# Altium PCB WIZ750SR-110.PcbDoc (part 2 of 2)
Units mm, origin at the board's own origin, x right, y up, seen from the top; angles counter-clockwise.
Board outline 63 x 45 mm, 4 copper layers (Top Layer, Internal Plane 1, Internal Plane 2, Bottom Layer); 95 components, 91 nets, 361 pads, 264 vias.
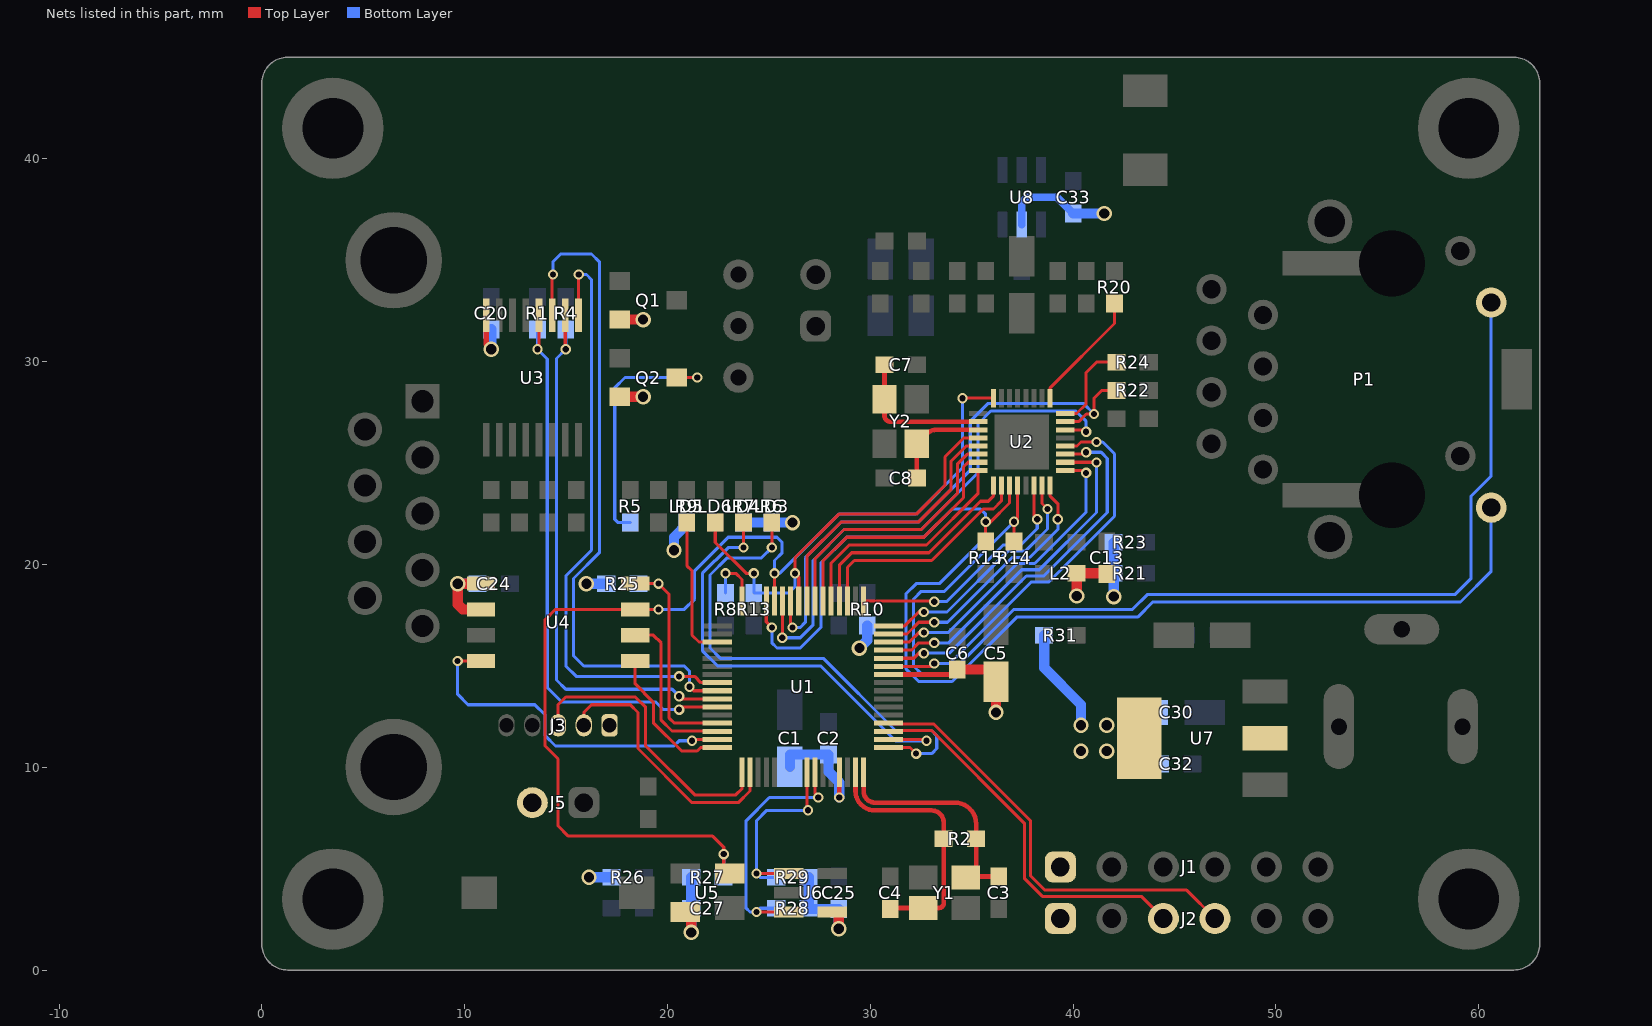
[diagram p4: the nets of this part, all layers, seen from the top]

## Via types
v1: diameter 0.762, hole 0.508, Top Layer to Bottom Layer, tented both sides, 186 vias
v2: diameter 0.508, hole 0.305, Top Layer to Bottom Layer, tented both sides, 78 vias

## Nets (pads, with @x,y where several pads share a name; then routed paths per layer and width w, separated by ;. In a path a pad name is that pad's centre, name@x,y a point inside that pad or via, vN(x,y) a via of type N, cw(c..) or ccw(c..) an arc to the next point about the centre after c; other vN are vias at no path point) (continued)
NetQ2_3: Q2.3 R5.1 | length 12.6
  Top Layer w0.152: Q2.3@20.45,29.21 v2(21.463,29.21)
  Bottom Layer w0.152: R5.1@18.161,22.06 17.564,22.06 17.399,22.225 17.399,28.702 17.907,29.21 v2(21.463,29.21)
NetR8_2: R8.2 U1.32 | length 3
  Top Layer w0.152: v2(22.86,19.558) 23.368,19.558 23.67,19.256 U1.32@23.67,18.195
  Bottom Layer w0.152: R8.2@22.86,18.58 v2(22.86,19.558)
NetR20_2: R20.2 U2.25 | length 6
  Top Layer w0.152: U2.25@38.865,28.185 38.865,28.705 42.037,31.877 R20.2@42.037,32.855
NetR24_2: R24.2 U2.24 | length 4.5
  Top Layer w0.152: U2.24@39.615,27.435 40.168,27.435 40.64,27.907 40.64,29.464 41.148,29.972 R24.2@42.126,29.972
PB_04: U1.24 U2.5 | length 13.7
  Top Layer w0.152: U1.24@26.87,18.195 26.87,20.393 28.575,22.098 32.385,22.098 33.985,23.698 33.985,25.095 34.725,25.835 U2.5@35.315,25.835
PB_05: LD6.2 R13.2 U1.25 U2.4 | length 21.8
  Top Layer w0.152: LD6.2@22.352,22.06 22.352,21.082 23.876,19.558 v2(24.257,19.558) ; U1.25@26.47,18.195 26.47,19.377 v2(26.289,19.558) 26.289,20.32 28.448,22.479 32.258,22.479 33.68,23.901 33.68,25.298 34.617,26.235 U2.4@35.315,26.235
  Bottom Layer w0.152: v2(24.257,19.558) R13.2@24.257,18.58 25.971,18.58 26.289,18.898 v2(26.289,19.558)
PB_06: U1.16 U2.15 | length 12.1
  Top Layer w0.152: U1.16@30.895,16.97 31.702,16.97 32.385,17.653 v2(32.639,17.653) ; U2.15@38.465,23.885 38.465,23.003 v2(38.735,22.733)
  Bottom Layer w0.152: v2(32.639,17.653) 33.782,17.653 36.779,20.65 37.643,20.65 38.735,21.742 v2(38.735,22.733)
PB_07: U1.17 U2.14 | length 12.2
  Top Layer w0.152: U1.17@29.67,18.195 33.113,18.195 v2(33.147,18.161) ; U2.14@38.065,23.885 38.065,22.387 v2(38.227,22.225)
  Bottom Layer w0.152: v2(33.147,18.161) 33.757,18.161 36.551,20.955 37.414,20.955 38.227,21.768 v2(38.227,22.225)
PB_09: U1.19 U2.10 | length 11.4
  Top Layer w0.152: U1.19@28.87,18.195 28.87,19.853 29.21,20.193 33.02,20.193 35.56,22.733 36.068,22.733 36.465,23.13 U2.10@36.465,23.885
PB_10: U1.20 U2.9 | length 11.3
  Top Layer w0.152: U1.20@28.47,18.195 28.47,19.961 29.083,20.574 32.893,20.574 35.433,23.114 35.814,23.114 36.065,23.365 U2.9@36.065,23.885
PB_11: U1.21 U2.8 | length 11.7
  Top Layer w0.152: U1.21@28.07,18.195 28.07,20.069 28.956,20.955 32.766,20.955 35.315,23.504 U2.8@35.315,24.635
PB_12: U1.22 U2.7 | length 12.5
  Top Layer w0.152: U1.22@27.67,18.195 27.67,20.177 28.829,21.336 32.639,21.336 34.595,23.292 34.595,24.81 34.82,25.035 U2.7@35.315,25.035
PB_13: U1.23 U2.6 | length 13.1
  Top Layer w0.152: U1.23@27.27,18.195 27.27,20.285 28.702,21.717 32.512,21.717 34.29,23.495 34.29,24.943 34.782,25.435 U2.6@35.315,25.435
PB_14: R22.1 U1.26 U2.23 | length 27.9
  Top Layer w0.152: U1.26@26.07,18.195 26.07,16.983 v2(26.162,16.891) ; U2.23@39.615,27.035 40.271,27.035 40.648,27.412 v2(41.027,27.412) 41.027,28.194 41.408,28.575 R22.1@42.126,28.575
  Bottom Layer w0.152: v2(26.162,16.891) 26.543,16.891 26.797,17.145 26.797,20.32 28.575,22.098 32.385,22.098 34.925,24.638 34.925,27.051 35.814,27.94 40.499,27.94 v2(41.027,27.412)
PB_15: U1.27 U2.22 | length 26.5
  Top Layer w0.152: v2(25.654,16.383) 25.67,16.399 U1.27@25.67,18.195 ; U2.22@39.615,26.635 40.548,26.635 v2(40.64,26.543)
  Bottom Layer w0.152: v2(25.654,16.383) 26.543,16.383 27.178,17.018 27.178,20.193 28.702,21.717 32.512,21.717 35.306,24.511 35.306,26.924 35.941,27.559 40.132,27.559 40.64,27.051 v2(40.64,26.543)
PD_00: U1.11 U2.20 | length 20
  Top Layer w0.152: U1.11@30.895,14.97 33.004,14.97 v2(33.147,15.113) ; U2.20@39.615,25.835 40.186,25.835 40.386,26.035 v2(41.148,26.035)
  Bottom Layer w0.152: v2(33.147,15.113) 33.909,15.113 37.922,19.126 38.786,19.126 42.037,22.377 42.037,25.451 41.453,26.035 v2(41.148,26.035)
PD_01: U1.12 U2.19 | length 18.7
  Top Layer w0.152: U1.12@30.895,15.37 32.134,15.37 32.385,15.621 v2(32.639,15.621) ; U2.19@39.615,25.435 40.548,25.435 v2(40.64,25.527)
  Bottom Layer w0.152: v2(32.639,15.621) 33.884,15.621 37.694,19.431 38.557,19.431 41.681,22.555 41.681,25.222 41.377,25.527 v2(40.64,25.527)
PD_02: U1.13 U2.18 | length 17.1
  Top Layer w0.152: U1.13@30.895,15.77 32.026,15.77 32.385,16.129 v2(33.147,16.129) ; U2.18@39.615,25.035 41.132,25.035 v2(41.148,25.019)
  Bottom Layer w0.152: v2(33.147,16.129) 33.858,16.129 37.465,19.736 38.329,19.736 41.148,22.555 v2(41.148,25.019)
PD_03: U1.14 U2.17 | length 15.4
  Top Layer w0.152: U1.14@30.895,16.17 31.918,16.17 32.385,16.637 v2(32.639,16.637) ; U2.17@39.615,24.635 40.516,24.635 v2(40.64,24.511)
  Bottom Layer w0.152: v2(32.639,16.637) 33.833,16.637 37.236,20.041 38.1,20.041 40.64,22.581 v2(40.64,24.511)
PD_04: U1.15 U2.16 | length 12.8
  Top Layer w0.152: U1.15@30.895,16.57 31.81,16.57 32.385,17.145 v2(33.147,17.145) ; U2.16@38.865,23.885 38.865,23.365 39.243,22.987 v2(39.243,22.225)
  Bottom Layer w0.152: v2(33.147,17.145) 33.807,17.145 37.008,20.345 37.871,20.345 39.243,21.717 v2(39.243,22.225)
PHY_AD0: P1.L4 R15.2 U1.29 U2.11 | length 65.5
  Top Layer w0.152: U1.29@24.87,18.195 24.87,17.167 v2(25.146,16.891) ; R15.2@35.687,21.12 v2(35.687,22.098) 35.941,22.098 36.865,23.022 U2.11@36.865,23.885
  Bottom Layer w0.152: v2(25.146,16.891) 25.146,16.129 25.4,15.875 26.543,15.875 27.559,16.891 27.559,20.066 28.829,21.336 32.639,21.336 34.036,22.733 35.433,22.733 35.687,22.479 v2(35.687,22.098) 35.687,21.336 33.401,19.05 32.258,19.05 31.75,18.542 31.75,14.859 32.385,14.224 34.036,14.224 37.211,17.399 43.18,17.399 43.923,18.142 59.097,18.142 60.61,19.655 P1.L4@60.61,22.8
PHY_AD3: P1.L2 R14.2 U2.12 | length 56.3
  Top Layer w0.152: R14.2@37.084,21.12 v2(37.084,22.098) 37.265,22.279 U2.12@37.265,23.885
  Bottom Layer w0.152: v2(37.084,22.098) 33.655,18.669 32.512,18.669 32.131,18.288 32.131,14.986 32.512,14.605 33.909,14.605 37.084,17.78 42.926,17.78 43.669,18.523 58.843,18.523 59.605,19.285 59.605,23.349 60.61,24.354 P1.L2@60.61,32.91
RESETN: R27.1 U1.28 U2.32 U4.3 U5.2 | length 55.3
  Top Layer w0.152: v2(19.558,17.78) U4.3@18.405,17.78 14.478,17.78 13.97,17.272 13.97,11.049 14.605,10.414 14.605,7.112 15.113,6.604 22.225,6.604 22.771,6.058 v2(22.771,5.715) 22.771,5.06 U5.2@23.071,4.76 ; U1.28@25.27,18.195 25.27,19.555 v2(25.273,19.558) ; v2(34.544,28.194) 36.056,28.194 U2.32@36.065,28.185
  Bottom Layer w0.152: v2(19.558,17.78) 20.828,17.78 21.336,18.288 21.336,19.685 22.987,21.336 25.4,21.336 25.654,21.082 25.654,20.574 25.273,20.193 v2(25.273,19.558) 25.527,19.558 28.448,22.479 32.258,22.479 34.544,24.765 v2(34.544,28.194) ; R27.1@22.771,4.572 v2(22.771,5.715)
SCL1: R29.1 U1.57 U6.1 | length 9.9
  Top Layer w0.152: v2(24.384,4.76) U6.1@25.976,4.76 ; U1.57@26.87,9.745 26.87,7.928 v2(26.924,7.874)
  Bottom Layer w0.152: R29.1@25.362,4.572 24.572,4.572 v2(24.384,4.76) 24.384,7.366 24.892,7.874 v2(26.924,7.874)
SDA1: R28.1 U1.58 U6.3 | length 12.9
  Top Layer w0.152: v2(24.384,2.86) U6.3@25.976,2.86 ; U1.58@27.27,9.745 27.27,8.671 v2(27.432,8.509)
  Bottom Layer w0.152: R28.1@25.362,3.048 24.572,3.048 v2(24.384,2.86) 24.064,2.86 23.876,3.048 23.876,7.366 25.019,8.509 v2(27.432,8.509)
SPI_MISO1: U1.47 U4.8 | length 17.4
  Top Layer w0.152: v2(9.652,15.24) U4.8@10.805,15.24 ; v2(21.209,11.303) 21.276,11.37 U1.47@22.445,11.37
  Bottom Layer w0.152: v2(9.652,15.24) 9.652,13.589 10.16,13.081 13.462,13.081 13.97,12.573 13.97,11.557 14.478,11.049 20.32,11.049 20.574,11.303 v2(21.209,11.303)
SPI_MOSI1: U1.48 U4.1 | length 7.2
  Top Layer w0.152: U4.1@18.405,15.24 18.405,14.107 19.304,13.208 19.304,12.192 20.701,10.795 21.463,10.795 21.638,10.97 U1.48@22.445,10.97
SPI_SCLK1: U1.46 U4.2 | length 8.2
  Top Layer w0.152: U4.2@18.405,16.51 19.304,16.51 19.685,16.129 19.685,12.319 20.221,11.783 22.445,11.783 U1.46@22.445,11.77
SPI_SSEL1: R25.1 U1.45 U4.4 | length 11.4
  Top Layer w0.152: U4.4@18.405,19.05 v2(19.558,19.05) 20.066,18.542 20.066,12.446 20.342,12.17 U1.45@22.445,12.17
  Bottom Layer w0.152: R25.1@18.58,19.05 v2(19.558,19.05)
STATUS: LD5.2 U1.35 | length 7
  Top Layer w0.152: LD5.2@20.955,22.06 20.955,19.939 21.209,19.685 21.209,16.51 21.549,16.17 U1.35@22.445,16.17
STATUS_LED0: LD3.2 U1.1 | length 24.6
  Top Layer w0.152: v2(25.146,20.828) LD3.2@25.146,22.06 ; U1.1@30.895,10.97 31.956,10.97 v2(32.258,10.668)
  Bottom Layer w0.152: v2(25.146,20.828) 24.638,20.32 22.943,20.32 22.098,19.475 22.098,15.875 22.606,15.367 27.686,15.367 31.242,11.811 33.02,11.811 33.274,11.557 33.274,10.922 33.02,10.668 v2(32.258,10.668)
STATUS_LED1: LD4.2 U1.2 | length 22.4
  Top Layer w0.152: v2(23.749,20.828) LD4.2@23.749,22.06 ; U1.2@30.895,11.37 32.699,11.37 v2(32.766,11.303)
  Bottom Layer w0.152: v2(23.749,20.828) 22.987,20.828 21.717,19.558 21.717,15.748 22.479,14.986 27.559,14.986 31.242,11.303 v2(32.766,11.303)
SWCLK: J3.3 U1.49 | length 14.3
  Top Layer w0.152: J3.3@14.605,12.065 14.605,13.081 14.986,13.462 18.415,13.462 18.923,12.954 18.923,11.049 21.336,8.636 23.368,8.636 23.67,8.938 U1.49@23.67,9.745
SWDIO: J3.2 U1.50 | length 13.2
  Top Layer w0.152: J3.2@15.875,12.065 15.875,12.7 16.256,13.081 18.161,13.081 18.542,12.7 18.542,10.922 21.209,8.255 23.495,8.255 24.07,8.83 U1.50@24.07,9.745
U_CTS0: U1.40 U3.9 | length 30.1
  Top Layer w0.152: U3.9@15.61,32.284 15.61,34.279 v2(15.621,34.29) ; v2(20.574,14.478) 21.336,14.478 21.644,14.17 U1.40@22.445,14.17
  Bottom Layer w0.152: v2(15.621,34.29) 16.002,34.29 16.256,34.036 16.256,20.701 14.986,19.431 14.986,14.986 15.494,14.478 v2(20.574,14.478)
U_RTS0: U1.41 U3.11 | length 33.5
  Top Layer w0.152: U3.11@14.31,32.284 14.31,34.249 v2(14.351,34.29) ; v2(21.082,13.97) 21.282,13.77 U1.41@22.445,13.77
  Bottom Layer w0.152: v2(14.351,34.29) 14.351,34.925 14.732,35.306 16.256,35.306 16.637,34.925 16.637,20.574 15.367,19.304 15.367,15.494 15.875,14.986 20.828,14.986 21.082,14.732 v2(21.082,13.97)
U_RXD0: R1.2 U1.43 U3.12 | length 28.4
  Top Layer w0.152: v2(13.589,30.607) 13.66,30.678 U3.12@13.66,32.284 ; v2(20.574,12.84) 20.704,12.97 U1.43@22.445,12.97
  Bottom Layer w0.152: R1.2@13.589,31.585 v2(13.589,30.607) 14.072,30.124 14.072,13.933 14.796,13.208 19.431,13.208 19.799,12.84 v2(20.574,12.84)
U_RXD2: J2.4 U1.4 | length 21.7
  Top Layer w0.152: U1.4@30.895,12.17 30.943,12.122 33.14,12.122 37.897,7.365 37.897,4.648 38.608,3.937 45.593,3.937 J2.4@46.99,2.54
U_TXD0: R4.2 U1.42 U3.10 | length 27.5
  Top Layer w0.152: U3.10@14.96,32.284 14.96,30.633 v2(14.986,30.607) ; v2(20.574,13.5) 20.704,13.37 U1.42@22.445,13.37
  Bottom Layer w0.152: R4.2@14.986,31.585 v2(14.986,30.607) 14.529,30.15 14.529,14.3 14.986,13.843 20.231,13.843 v2(20.574,13.5)
U_TXD2: J2.3 U1.3 | length 19
  Top Layer w0.152: U1.3@30.895,11.77 30.943,11.818 33.013,11.818 37.592,7.239 37.592,4.522 38.482,3.632 43.358,3.632 J2.3@44.45,2.54
VCC_3.3V: C1.1 C2.2 C5.1 C6.2 C13.2 C20.2 C24.1 C25.2 C27.2 C30.1 C32.2 C33.1 J1.1 J2.1 J3.1 J5.2 L2.1 Q1.2 Q2.2 R6.2 R7.2 R9.2 R10.2 R21.1 R23.1 R25.2 R26.2 R27.2 R28.2 R29.2 R31.1 U1.10 U1.61 U3.16 U4.5 U4.6 U5.4 U6.4 U7.2 U7.4 U8.5 | length 55.5
  Top Layer w0.229: v2(28.47,8.509) U1.61@28.47,9.745 ; U1.10@30.895,14.57 34.039,14.57 C6.2@34.29,14.821
  Top Layer w0.254: U3.16@11.06,32.284 11.06,30.85 v1(11.303,30.607)
  Top Layer w0.508: U4.6@10.805,17.78 9.906,17.78 9.652,18.034 v1(9.652,19.05) U4.5@10.805,19.05 ; Q2.2@17.65,28.26 v1(18.796,28.26) ; Q1.2@17.65,32.07 v1(18.796,32.07) ; U5.4@20.871,2.86 21.171,2.56 v1(21.171,1.854) ; U6.4@28.126,2.86 28.448,2.86 v1(28.448,2.032) ; C6.2@34.29,14.821 36.195,14.821 C5.1@36.195,14.221 v1(36.195,12.7) ; v1(40.17,18.44) L2.1@40.17,19.558 41.618,19.558 C13.2@41.656,19.52
  Bottom Layer w0.381: U8.5@37.465,36.76 37.465,37.846 37.719,38.1 39.205,38.1 C33.1@40.005,37.3
  Bottom Layer w0.508: v1(9.652,19.05) C24.1@10.63,19.05 ; v1(11.303,30.607) C20.2@11.303,31.585 ; v1(16.002,19.05) R25.2@16.98,19.05 ; v1(16.129,4.572) R26.2@17.234,4.572 ; v1(20.32,20.701) 20.32,21.344 20.955,21.979 R9.2@20.955,22.06 ; v1(21.171,1.854) C27.2@21.171,3.048 R27.2@21.171,4.572 ; R7.2@23.749,22.06 R6.2@25.146,22.06 v1(26.162,22.06) ; C1.1@26.035,10.03 26.035,10.63 C2.2@27.94,10.63 27.94,9.779 28.47,9.249 v2(28.47,8.509) ; R29.2@26.962,4.572 R28.2@26.962,3.048 27,3.01 C25.2@28.448,3.01 v1(28.448,2.032) ; v1(29.464,15.875) 29.845,16.256 R10.2@29.845,16.98 ; R31.1@38.57,16.51 38.57,14.897 40.386,13.081 v1(40.386,12.065) ; C33.1@40.005,37.3 v1(41.529,37.3) ; v1(41.999,18.415) R21.1@41.999,19.558 R23.1@41.999,21.082
  other v1: 40.386,10.795 41.656,10.795 41.656,12.065
XIN: C4.2 R2.2 U1.63 Y1.3 | length 12.9
  Top Layer w0.229: U1.63@29.27,9.745 29.27,8.825 ccw(c30.226,8.825) 30.226,7.869 33.02,7.869 cw(c33.02,7.272) 33.617,7.272 R2.2@33.617,6.477 33.617,3.302 cw(c33.375,3.302) 33.375,3.06 Y1.3@32.605,3.06 31.038,3.06 ccw(c31.038,3.01) C4.2@30.988,3.01
XOUT: C3.2 R2.1 U1.64 Y1.1 | length 11.8
  Top Layer w0.229: U1.64@29.67,9.745 29.67,8.811 ccw(c30.226,8.811) 30.226,8.255 34.163,8.255 cw(c34.163,7.201) 35.217,7.201 R2.1@35.217,6.477 35.217,5.072 cw(c34.755,5.072) 34.755,4.61 C3.2@36.322,4.61
XTAL1: C7.2 U2.2 Y2.1 | length 7.3
  Top Layer w0.229: C7.2@30.696,29.845 Y2.1@30.696,28.151 30.696,27.327 ccw(c30.988,27.327) 30.988,27.035 U2.2@35.315,27.035
XTAL2: C8.2 U2.3 Y2.3 | length 5
  Top Layer w0.229: C8.2@32.296,24.257 Y2.3@32.296,25.951 32.795,26.45 cw(c33.242,26.002) 33.242,26.635 U2.3@35.315,26.635
pads on no net: P1. P1.R4 P1.R5 P1.R6 P2.1 P2.4 P2.6 P2.9 SW2.2 U1.30 U1.31 U1.33 U1.34 U1.38 U1.44 U1.51 U1.52 U1.53 U1.54 U1.55 U1.56 U1.59 U1.60 U2.1 U2.21

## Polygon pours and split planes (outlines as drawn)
CH_GND on Top Layer "Top Layer-NET" (solid, remove dead copper, pour order 18): 62.103,37.211 54.483,37.211 53.34,36.068 51.943,36.068 50.8,37.211 46.99,37.211 46.736,37.465 46.736,41.91 46.482,42.164 9.398,42.164 9.186,41.952 9.144,41.91 9.144,40.188 9.144,31.242 8.89,30.988 2.921,30.988 2.667,30.734 2.667,14.224 2.921,13.97 8.89,13.97 9.144,13.716 9.144,7.493 8.89,7.239 7.493,7.239 7.239,6.985 7.239,0.889 6.985,0.635 0.889,0.635 0.635,0.889 0.635,44.069 0.889,44.323 62.103,44.323 62.357,44.069 62.357,37.465 62.103,37.211
5V on Top Layer "Top Layer-NET" (solid, remove dead copper, pour order 0): 53.848,14.478 53.848,10.16 53.594,9.906 51.689,9.906 51.435,10.16 51.435,12.7 51.181,12.954 50.927,12.954 46.99,12.954 46.736,13.208 46.736,17.272 46.99,17.526 53.594,17.526 53.848,17.272
VCC_3.3V on Top Layer "Top Layer-NET" (solid, remove dead copper, pour order 4): 49.657,12.319 50.546,12.319 50.8,12.065 50.8,11.938 50.8,10.795 50.546,10.541 50.292,10.541 46.609,10.541 46.355,10.287 46.355,10.16 46.355,8.382 46.101,8.128 45.974,8.128 40.005,8.128 39.751,8.382 39.751,8.509 39.751,14.478 40.005,14.732 40.132,14.732 46.101,14.732 46.355,14.478 46.355,14.351 46.355,12.573 46.609,12.319
GND on Top Layer "Top Layer-GND" (solid, remove dead copper, pour order 16): 9.906,29.591 4.445,29.591 4.191,29.337 4.191,27.559 4.191,16.002 4.445,15.748 4.699,15.748 10.414,15.748 10.668,15.494 10.668,15.24 10.668,5.969 10.414,5.715 10.16,5.715 9.017,5.715 8.763,5.461 8.763,5.207 8.763,1.016 9.017,0.762 9.144,0.762 53.721,0.762 53.975,1.016 53.975,1.143 53.975,8.763 54.229,9.017 54.356,9.017 62.103,9.017 62.357,9.271 62.357,9.525 62.357,17.78 62.103,18.034 61.849,18.034 45.466,18.034 45.212,18.288 45.212,18.542 45.212,40.513 44.958,40.767 44.704,40.767 10.922,40.767 10.668,40.513 10.668,40.132 10.668,29.845 10.414,29.591
GND on Top Layer "Top Layer-GND" (solid, remove dead copper, pour order 22): 33.401,32.131 33.401,30.353 34.798,28.956 41.91,28.956 42.037,29.083 42.037,32.131
CH_GND on Bottom Layer "Top Layer-NET" (solid, remove dead copper, pour order 20): 62.357,42.037 62.357,37.465 62.103,37.211 54.864,37.211 54.61,36.957 54.61,20.32 54.356,20.066 50.927,20.066 50.673,20.32 50.673,36.957 50.419,37.211 46.99,37.211 46.736,37.465 46.736,41.91 46.482,42.164 9.398,42.164 9.144,41.91 9.144,31.242 8.89,30.988 2.921,30.988 2.667,30.734 2.667,14.224 2.921,13.97 8.89,13.97 9.144,13.716 9.144,7.493 8.906,7.255 7.509,7.255 7.239,6.985 7.239,0.889 6.985,0.635 0.889,0.635 0.635,0.889 0.635,44.069 0.889,44.323 62.103,44.323 62.357,44.069
5V on Bottom Layer "Top Layer-NET" (solid, remove dead copper, pour order 2): 51.435,16.764 51.435,14.859 51.181,14.605 49.911,14.605 46.99,14.605 46.736,14.859 46.736,17.272 46.99,17.526 51.181,17.526 51.435,17.272
VCC_3.3V on Bottom Layer "Top Layer-NET" (solid, remove dead copper, pour order 6): 44.704,12.319 44.704,9.652 44.45,9.398 44.323,9.398 40.005,9.398 39.751,9.652 39.751,9.779 39.751,13.462 40.005,13.716 40.259,13.716 44.45,13.716 44.704,13.462
GND on Bottom Layer "Top Layer-GND" (solid, remove dead copper, pour order 14): 9.906,29.591 4.445,29.591 4.191,29.337 4.191,27.559 4.191,16.002 4.445,15.748 4.699,15.748 10.414,15.748 10.668,15.494 10.668,15.24 10.668,5.969 10.414,5.715 10.16,5.715 9.017,5.715 8.763,5.461 8.763,5.207 8.763,1.016 9.017,0.762 9.144,0.762 53.721,0.762 53.975,1.016 53.975,1.143 53.975,8.763 54.229,9.017 54.356,9.017 62.103,9.017 62.357,9.271 62.357,9.525 62.357,17.78 62.103,18.034 61.849,18.034 45.466,18.034 45.212,18.288 45.212,18.542 45.212,40.513 44.958,40.767 44.704,40.767 10.922,40.767 10.668,40.513 10.668,40.132 10.668,29.845 10.414,29.591
GND on Bottom Layer "Top Layer-GND" (solid, remove dead copper, pour order 24): 10.414,29.591 4.445,29.591 4.191,29.337 4.191,16.002 4.445,15.748 10.033,15.748 10.414,16.129
GND on Internal Plane 1 (split plane): 45.21,18.669 45.219,18.549 45.247,18.433 45.293,18.322 45.356,18.22 45.434,18.129 45.525,18.051 45.627,17.988 45.738,17.942 45.854,17.914 45.974,17.905 62.49,17.905 62.49,8.89 53.975,8.89 53.975,0.51 8.765,0.51 8.765,5.586 9.906,5.586 10.026,5.595 10.142,5.623 10.253,5.669 10.355,5.732 10.446,5.81 10.524,5.901 10.587,6.003 10.633,6.114 10.661,6.23 10.67,6.35 10.67,14.859 10.661,14.979 10.633,15.095 10.587,15.206 10.524,15.308 10.446,15.399 10.355,15.477 10.253,15.54 10.142,15.586 10.026,15.614 9.906,15.623 4.193,15.623 4.193,29.462 9.906,29.462 10.026,29.471 10.142,29.499 10.253,29.545 10.355,29.608 10.446,29.686 10.524,29.777 10.587,29.879 10.633,29.99 10.661,30.106 10.67,30.226 10.67,40.638 45.21,40.638
IP_3.3V on Internal Plane 2 (split plane): 37.146,33.655 37.152,33.593 37.17,33.533 37.2,33.478 37.239,33.429 37.288,33.39 37.343,33.36 37.403,33.342 37.465,33.336 45.212,33.336 45.212,33.299 41.25,33.299 41.25,31.979 45.212,31.979 45.212,23.941 39.37,23.941 39.308,23.935 39.248,23.917 39.193,23.887 39.144,23.848 39.105,23.799 39.075,23.744 39.057,23.684 39.051,23.622 39.051,17.972 35.117,17.972 35.117,30.861 35.111,30.923 35.093,30.983 35.063,31.038 35.024,31.087 34.975,31.126 34.92,31.156 34.86,31.174 34.798,31.18 28.767,31.18 28.767,37.4 37.146,37.4
VCC_3.3V on Internal Plane 2 (split plane): 45.212,33.974 37.784,33.974 37.784,37.719 37.778,37.781 37.76,37.841 37.73,37.896 37.691,37.945 37.642,37.984 37.587,38.014 37.527,38.032 37.465,38.038 28.448,38.038 28.386,38.032 28.326,38.014 28.271,37.984 28.222,37.945 28.183,37.896 28.153,37.841 28.135,37.781 28.129,37.719 28.129,30.861 28.135,30.799 28.153,30.739 28.183,30.684 28.222,30.635 28.271,30.596 28.326,30.566 28.386,30.548 28.448,30.542 34.479,30.542 34.479,17.653 34.485,17.591 34.503,17.531 34.533,17.476 34.572,17.427 34.621,17.388 34.676,17.358 34.736,17.34 34.798,17.334 39.37,17.334 39.432,17.34 39.492,17.358 39.547,17.388 39.596,17.427 39.635,17.476 39.665,17.531 39.683,17.591 39.689,17.653 39.689,23.303 45.212,23.303 45.212,17.907 62.49,17.907 62.49,8.89 53.975,8.89 53.975,0.51 8.763,0.51 8.763,5.588 10.668,5.588 10.668,15.621 4.191,15.621 4.191,29.464 10.668,29.464 10.668,40.64 45.212,40.64

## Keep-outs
Keep-Out Layer:
  the board outline again, w0.127
  text ".Layer_Name" at 9.398,49.53 h1.52

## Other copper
Top Layer:
  pour cut-out: 7.747,20.701 4.953,20.701 4.953,17.907 7.747,17.907
  pour cut-out: 41.91,26.67 41.91,23.876 41.656,23.622 40.386,23.622 40.132,23.368 40.132,22.073 40.259,21.946 40.865,21.946 40.132,21.717 39.116,21.717 39.116,26.416 39.37,26.67
  pour cut-out: 38.735,17.272 36.957,17.272 36.957,18.669 38.735,18.669
  pour cut-out: 31.108,23.622 31.108,23.069 30.899,22.86 32.004,22.86 32.004,23.622
  pour cut-out: 18.466,30.447 18.466,31.267 18.618,31.267 18.593,31.242 18.593,30.447 18.814,30.226 22.098,30.226 22.243,30.371 22.243,31.622 23.367,31.622 23.495,31.75 23.622,31.623 23.622,28.956 18.466,28.956
  pour cut-out: 32.334,7.239 26.987,7.239 26.924,7.302 26.924,8.255 32.563,8.255 32.918,8.255 32.918,6.883 32.918,5.461 32.334,5.461 32.563,5.69 32.563,7.01
  pour cut-out: 31.648,2.079 30.15,2.079 30.15,4.356 31.648,4.356
  pour cut-out: 19.761,8.204 19.837,8.28 20.49,8.28 20.676,8.169 20.676,8.306 19.761,8.306
  pour cut-out: 24.054,2.079 27.563,2.079 27.813,1.829 27.813,2.21 25.933,2.21 24.054,2.21
  pour cut-out: 24.125,5.641 24.651,5.641 24.914,5.378 24.123,5.378
  pour cut-out: 14.224,28.55 13.843,28.931 13.843,29.464 14.224,29.845 16.307,29.845 16.866,29.286 16.866,29.972 13.64,29.972 13.64,28.55
  pour cut-out: 21.309,28.379 22.775,28.379 22.826,28.328 22.902,28.485 22.826,28.561 21.303,28.561
  pour cut-out: 16.789,24.841 16.789,25.425 17.501,26.137 17.501,27.305 17.666,27.47 16.967,28.169 16.434,27.635 15.596,27.635 15.342,27.889 15.342,27.635 15.342,24.841
  pour cut-out: 28.55,22.945 26.183,22.945 25.832,23.296 25.832,22.936 25.832,22.784 25.883,22.784 28.55,22.784
  pour cut-out: 25.988,26.559 25.988,22.878 25.877,22.767 25.844,22.8 25.844,26.559
  pour cut-out: 24.816,32.029 25.806,32.029 25.806,31.775 24.816,31.775
  pour cut-out: 29.718,29.108 29.718,30.484 29.87,30.636 29.87,29.108
  pour cut-out: 32.55,30.636 32.883,30.969 32.883,32.002 32.791,32.094 33.045,32.094 33.045,30.968 33.045,30.632
  pour cut-out: 38.097,36.51 38.191,36.604 38.191,37.368 38.079,37.48 38.5,37.48 38.5,36.51
  pour cut-out: 44.524,29.571 44.592,29.504 45.268,29.503 45.336,29.571 45.336,29.309 44.524,29.309
  pour cut-out: 44.036,26.387 45.118,26.387 45.302,26.203 45.302,26.496 44.036,26.496
  pour cut-out: 37.201,12.894 37.201,10.917 37.448,10.67 39.048,10.67 39.487,11.109 39.487,12.894 39.274,12.681 37.414,12.68
  pour cut-out: 49.995,6.883 49.995,7.634 50.53,8.169 49.777,8.169 49.777,6.889
  pour cut-out: 45.418,17.409 45.466,17.457 45.466,18.338 45.743,18.338 45.743,17.409 45.705,17.409
  pour cut-out: 26.259,8.671 26.259,8.668 26.444,8.483 26.444,8.671
  pour cut-out: 26.772,32.715 26.772,33.401 27.94,33.401 27.94,32.715
  pour cut-out: 29.693,33.299 29.693,37.059 30.099,37.465 32.817,37.465 33.122,37.16 33.122,33.299 31.801,33.299 31.674,33.426 31.318,33.426 31.191,33.299
  pour cut-out: 19.569,33.851 18.619,34.801 18.115,34.801 18.115,33.85 18.115,32.628 19.569,32.628
  pour cut-out: 13.36,34.239 13.589,34.011 13.589,33.401 13.767,33.401 13.767,34.239
  pour cut-out: 11.049,33.426 10.592,33.884 10.592,33.426
  pour cut-out: 40.716,16.586 41.721,16.586 41.721,16.758 42.621,18.085 40.716,18.085
  pour cut-out: 33.909,16.891 33.909,18.237 34.366,18.694 34.95,18.694 34.95,18.999 34.468,18.999 33.528,18.999 33.528,18.796 33.528,16.891
  text ".Layer_Name" at 9.398,49.53 h1.52
Bottom Layer:
  pour cut-out: 35.902,25.328 35.902,23.661 36.068,23.495 39.497,23.495 39.751,23.749 39.751,27.178 40.767,27.178 40.767,22.174 40.564,21.971 35.052,21.971 35.052,25.146 34.925,25.273
  pour cut-out: 43.053,29.591 45.034,29.591 45.466,30.023 45.466,29.591 45.466,28.956 45.37,28.86 43.053,28.86
  pour cut-out: 44.196,21.971 45.593,21.971 45.72,21.844 45.72,20.828 44.45,20.828 44.196,21.082
  pour cut-out: 37.973,34.671 39.243,34.671 39.243,35.306 37.973,35.306
  pour cut-out: 41.021,35.687 41.021,36.703 39.624,36.703 39.624,35.687
  pour cut-out: 25.908,23.216 26.137,22.987 28.448,22.987 28.448,21.717 28.321,21.59 25.908,21.59
  pour cut-out: 18.796,31.173 17.468,31.173 17.272,31.369 17.272,32.385 18.796,32.385
  pour cut-out: 35.433,15.113 35.814,15.494 35.814,22.606 27.813,22.606 27.813,15.875 28.575,15.113
  pour cut-out: 44.856,31.953 45.39,31.953 45.39,31.42
  pour cut-out: 25.044,5.258 25.044,5.334 24.816,5.563 24.816,5.258
  pour cut-out: 18.136,0.686 18.339,0.889 18.339,2.134 18.161,2.311 18.517,2.311 18.517,0.686
  pour cut-out: 10.592,12.37 10.744,12.522 11.328,12.522 11.328,12.624 10.592,12.624
  pour cut-out: 12.598,10.719 12.598,11.227 12.497,11.328 12.878,11.328 12.878,10.719
  pour cut-out: 14.91,29.693 15.088,29.87 15.85,29.87 15.926,29.794 15.926,29.972 14.91,29.972
  pour cut-out: 10.236,29.591 13.284,29.591 13.691,29.185 13.691,29.82 10.236,29.82
  pour cut-out: 11.963,32.842 12.167,32.639 12.751,32.639 12.954,32.842 12.954,32.512 11.963,32.512
  pour cut-out: 50.267,0.596 50.025,0.838 50.025,1.43 50.275,1.68 49.826,1.68 49.826,0.596
  pour cut-out: 36.418,28.233 36.674,28.489 36.674,28.906 36.356,29.224 36.674,29.224 36.996,29.224 36.996,28.233
  pour cut-out: 35.906,28.406 35.18,28.406 35.114,28.472 35.114,28.313 35.906,28.313
  pour cut-out: 10.585,13.812 10.934,13.463 10.585,13.463
  pour cut-out: 35.579,32.302 35.725,32.156 36.618,32.156 36.73,32.268 36.73,31.885 35.579,31.885
  pour cut-out: 38.248,32.079 38.248,30.192 38.636,29.804 38.068,29.804 38.068,29.983 38.068,32.079
  pour cut-out: 29.474,33.299 29.474,36.84 30.251,37.617 32.664,37.617 33.518,36.764 33.518,33.299 31.801,33.299 31.674,33.426 31.318,33.426 31.191,33.299
  pour cut-out: 25.937,24.486 25.937,24.761 25.349,25.349 17.958,25.349 18.009,25.298 18.009,24.486
  text ".Layer_Name" at 9.398,49.53 h1.52
Internal Plane 1 (plane layer: these items are gaps in the copper):
  rectangle: 45.564,23.364 50.644,34.794
  rectangle: 53.975,0 62.992,8.89
  region: 8.001,0 8.001,6.35 9.906,6.35 9.906,14.859 3.429,14.859 3.429,30.226 9.906,30.226 9.906,41.402 45.974,41.402 45.974,18.669 63,18.669 63,45 0,45 0,0
  lines w1.524: 8.001,0.381 8.001,6.35 9.906,6.35 9.906,14.859 3.429,14.859 3.429,30.226 9.906,30.226 9.906,41.402 45.974,41.402 45.974,18.669 62.738,18.669
  text "GND" at 9.398,49.562 h1.52
Internal Plane 2 (plane layer: these items are gaps in the copper):
  rectangle: 31.877,2.413 35.433,5.207
  rectangle: 30.099,25.273 32.893,28.829
  rectangle: 45.564,23.364 50.644,34.794
  rectangle: 53.975,0 62.992,8.89
  region: 8.763,0 8.763,5.588 10.668,5.588 10.668,15.621 4.191,15.621 4.191,29.464 10.668,29.464 10.668,40.64 45.212,40.64 45.212,17.907 63,17.907 63,45 0,45 0,0
  lines w0.635: 28.448,30.861 28.448,37.719 37.465,37.719 37.465,33.655 45.593,33.655 45.593,23.622 39.37,23.622 39.37,17.653 34.798,17.653 34.798,30.861 28.448,30.861
  text "POWER" at 9.398,49.562 h1.52
  text "IP_3.3V" at 41.402,32.385 h0.76
  text "VCC_3.3V" at 9.017,1.016 h0.76

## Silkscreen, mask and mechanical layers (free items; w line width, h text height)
Top Overlay:
  rectangle: 10.16,37.465 36.16,44.465
  text ".Layer_Name" at 9.398,49.562 h1.52
  text "WIZ750SR-110 V1.0" at 45.288,39.421 h1.52
  text "OFF" at 21.971,34.925 h0.76 r90
  text "APP" at 26.289,28.321 h0.76
  text "BOOT" at 26.035,27.305 h0.76
  text "ON" at 21.971,26.924 h0.76 r90
  text "HW" at 22.733,25.654 h0.76
  text "TRIG" at 22.479,24.638 h0.76
  text "TX" at 26.797,22.987 h0.76 r90
  text "RX" at 27.813,22.987 h0.76 r90
  text "COL" at 29.845,22.987 h0.76 r90
  text "BOOT" at 13.208,5.969 h0.76
  text "Reset" at 14.859,0.889 h0.76
Bottom Overlay:
  lines w0.2: 14.304,39.394 25.455,39.394 ; 15.93,36.854 25.455,36.854 ; 16.057,38.124 25.455,38.124
  text ".Layer_Name" at 9.398,49.53 h1.52
  text "WIZ750SR-110" at 25.455,39.648 h1.2
  text "http://wizwiki.net" at 25.455,38.505 h1
  text "Designed by WIZnet" at 25.455,37.235 h1
  text "GND" at 12.446,16.129 h0.76 r90
  text "RESET" at 13.716,16.129 h0.76 r90
  text "SWCLK" at 14.986,16.129 h0.76 r90
  text "SWDIO" at 16.256,16.129 h0.76 r90
  text "3.3V" at 17.526,16.129 h0.76 r90
  text "SWD" at 20.193,11.684 h0.76
  text "Expansion GPIO" at 38.1,4.699 h0.76
  text "ISP Port" at 38.1,2.159 h0.76
  text "3.3V" at 40.132,0.508 h0.76
  text "BOOT" at 43.307,0.508 h0.76
  text "TX" at 44.958,0.508 h0.76
  text "RX" at 47.498,0.508 h0.76
  text "RSTn" at 50.673,0.508 h0.76
  text "GND" at 53.086,0.508 h0.76
Top Paste:
  text ".Layer_Name" at 9.398,49.53 h1.52
Bottom Paste:
  text ".Layer_Name" at 9.398,49.53 h1.52
Top Solder:
  text ".Layer_Name" at 9.398,49.53 h1.52
Bottom Solder:
  text ".Layer_Name" at 9.398,49.53 h1.52
Drill Guide:
  text ".Layer_Name" at 9.398,49.53 h1.52
Mechanical 2:
  lines w0.127: 71.831,16.129 97.993,16.129 ; 71.831,18.923 97.993,18.923 ; 0,1.27 ccw(c1.27,1.27) 1.27,0 61.73,0 ccw(c61.73,1.27) 63,1.27 63,43.73 ccw(c61.73,43.73) 61.73,45 1.27,45 ccw(c1.27,43.73) 0,43.73 0,1.27 ; 70.485,4.775 ccw(c71.196,4.775) 71.196,4.064 98.374,4.064 ccw(c98.374,4.775) 99.085,4.775 99.085,24.003 ccw(c98.374,24.003) 98.374,24.714 71.196,24.714 ccw(c71.196,24.003) 70.485,24.003 70.485,4.775
  text "BOARD NAME : WIZ750SR-110" at 0,60.706 h1.52
  text "VERSION : V1.0" at 0,57.912 h1.52
  text "SIZE : 63mX45mX1.6T" at 0,55.118 h1.52
  text "GERBER DATE : 2017.12.27" at 0,52.324 h1.52
  text "LAYER :" at 0,49.53 h1.52
  text "Layer Stack Up Detail for:" at 71.958,22.606 h1.02
  text "WIZ750SR-110 V1.0.PcbDoc" at 71.831,20.193 h1.27
  text "Layer Name : 4L  1.6T" at 71.958,17.018 h1.02
  text "Top Layer" at 71.831,13.335 h1.52
  text "GND" at 71.831,10.541 h1.52
  text "POWER" at 71.831,7.874 h1.52
  text "Bottom Layer" at 71.831,5.334 h1.52
  text "KS Technology artwork" at 70.485,0 h5.08
Drill Drawing:
  text ".Layer_Name" at 9.398,49.53 h1.52
  text ".Legend" at 72.517,27.432 h1.02

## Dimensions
0,1.27 to 63,1.27 on Mechanical 2
1.27,0 to 1.27,45 on Mechanical 2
